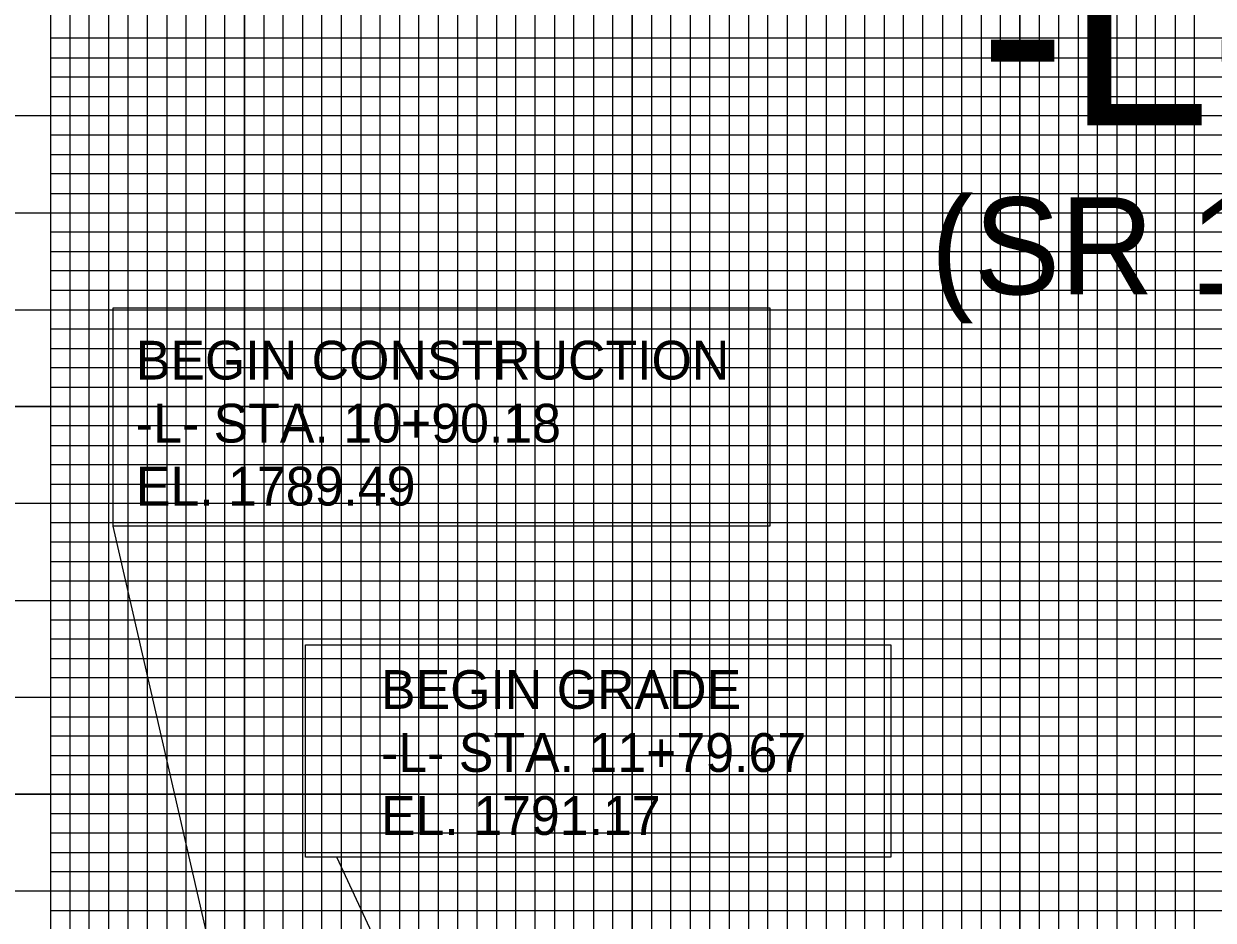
# Model space of a CAD drawing. Extents: x 572269 to 579912, y -56875 to -49627.
# Drawn here: x 573877.8 to 574184.5, y -53080.2 to -52849 of the extents above; entities that cross this region are included whole.
import ezdxf

# ---------------------------------------------------------------- set-up
doc = ezdxf.new("R2010")
doc.units = 0
for name, color, linetype in [('Prop Grid Mask', 7, 'Continuous'), ('Prop PFL Text', 7, 'Continuous'), ('Sheet Cutting Line CELL', 7, 'Continuous'), ('Sheet DOT Grid CELL', 7, 'Continuous'), ('Sheet Layout Profile Border', 7, 'Continuous'), ('Sheet Profile Grid Major CELL', 7, 'Continuous'), ('Sheet Profile Grid Middle CELL', 7, 'Continuous'), ('Sheet Profile Grid Minor CELL', 7, 'Continuous')]:
    doc.layers.add(name, color=color, linetype=linetype)

# ---------------------------------------------------------------- blocks, each defined once
blk = doc.blocks.new('PROFILE SHEET SINGLE')
at = {"layer": 'Sheet DOT Grid CELL'}
for p, q in [((1, 21), (1, 0.5)), ((2, 21), (2, 0.5)), ((3, 21), (3, 0.5)), ((4, 21), (4, 0.5)), ((5, 21), (5, 0.5)), ((6, 21), (6, 0.5)), ((0, 18.5), (25.999, 18.5)), ((0, 17.5), (30, 17.5)), ((0, 16.5), (30, 16.5)), ((0, 15.5), (30, 15.5))]:
    blk.add_line(p, q, dxfattribs=at)
at = {"layer": 'Sheet Profile Grid Major CELL'}
for points in [[(1, 21), (1, 0.5), (2, 0.5), (2, 21)], [(3, 21), (3, 0.5), (4, 0.5), (4, 21)], [(5, 21), (5, 0.5), (6, 0.5), (6, 21)], [(30, 17.5), (0, 17.5), (0, 18.5), (25.999, 18.5)], [(30, 15.5), (0, 15.5), (0, 16.5), (30, 16.5)]]:
    blk.add_lwpolyline(points, dxfattribs=at)
at = {"layer": 'Sheet Profile Grid Middle CELL'}
for points in [[(1.5, 0.5), (1.5, 21)], [(2.5, 21), (2.5, 0.5), (3.5, 0.5), (3.5, 21)], [(4.5, 21), (4.5, 0.5), (5.5, 0.5), (5.5, 21)], [(6.5, 21), (6.5, 0.5), (7.5, 0.5), (7.5, 21)], [(25.999, 19), (0, 19), (0, 17.999), (30, 17.999)], [(30, 17), (0, 17), (0, 16), (30, 16)], [(30, 15), (0, 15), (0, 14), (30, 14)]]:
    blk.add_lwpolyline(points, dxfattribs=at)
at = {"layer": 'Sheet Profile Grid Minor CELL'}
for p, q in [((29, 17.4), (1, 17.4)), ((1, 17.4), (1, 17.3)), ((1, 17.3), (29, 17.3)), ((29, 16.9), (1, 16.9))]:
    blk.add_line(p, q, dxfattribs=at)
for points in [[(1.1, 21), (1.1, 0.5), (1.2, 0.5), (1.2, 21)], [(1.3, 21), (1.3, 0.5), (1.4, 0.5), (1.4, 21)], [(1.6, 21), (1.6, 0.5), (1.7, 0.5), (1.7, 21)], [(1.8, 21), (1.8, 0.5), (1.9, 0.5), (1.9, 21)], [(2.1, 21), (2.1, 0.5), (2.2, 0.5), (2.2, 21)], [(2.3, 21), (2.3, 0.5), (2.4, 0.5), (2.4, 21)], [(2.6, 21), (2.6, 0.5), (2.7, 0.5), (2.7, 21)], [(2.8, 21), (2.8, 0.5), (2.9, 0.5), (2.9, 21)], [(3.1, 21), (3.1, 0.5), (3.2, 0.5), (3.2, 21)], [(3.3, 21), (3.3, 0.5), (3.4, 0.5), (3.4, 21)], [(3.6, 21), (3.6, 0.5), (3.7, 0.5), (3.7, 21)], [(3.8, 21), (3.8, 0.5), (3.9, 0.5), (3.9, 21)], [(4.1, 21), (4.1, 0.5), (4.2, 0.5), (4.2, 21)], [(4.3, 21), (4.3, 0.5)], [(4.3, 0.5), (4.4, 0.5), (4.4, 21)], [(4.6, 21), (4.6, 0.5), (4.7, 0.5), (4.7, 21)], [(4.8, 21), (4.8, 0.5), (4.9, 0.5), (4.9, 21)], [(5.1, 21), (5.1, 0.5), (5.2, 0.5), (5.2, 21)], [(5.3, 21), (5.3, 0.5), (5.4, 0.5), (5.4, 21)], [(5.6, 21), (5.6, 0.5), (5.7, 0.5), (5.7, 21)], [(5.8, 21), (5.8, 0.5), (5.9, 0.5), (5.9, 21)], [(6.1, 21), (6.1, 0.5), (6.2, 0.5), (6.2, 21)], [(6.3, 21), (6.3, 0.5), (6.4, 0.5), (6.4, 21)], [(6.6, 21), (6.6, 0.5), (6.7, 0.5), (6.7, 21)], [(6.8, 21), (6.8, 0.5), (6.9, 0.5), (6.9, 21)], [(25.999, 19.4), (1, 19.4), (1, 19.3), (25.999, 19.3)], [(25.999, 19.2), (1, 19.2), (1, 19.1), (25.999, 19.1)], [(25.999, 18.9), (1, 18.9), (1, 18.8), (25.999, 18.8)], [(25.999, 18.7), (1, 18.7), (1, 18.6), (25.999, 18.6)], [(25.999, 18.4), (1, 18.4), (1, 18.3), (25.999, 18.3)], [(29, 18.2), (1, 18.2), (1, 18.2), (1, 17.8), (29, 17.8)], [(1, 18.1), (29, 18.1)], [(29, 17.9), (1, 17.9)], [(29, 17.7), (1, 17.7), (1, 17.6), (29, 17.6)], [(29, 17.2), (1, 17.2), (1, 17.1), (29, 17.1)], [(29, 16.8), (1, 16.8), (1, 16.7), (29, 16.7)], [(29, 16.6), (1, 16.6)], [(1, 16.4), (29, 16.4)], [(29, 16.3), (1, 16.3), (1, 16.2), (29, 16.2)], [(29, 16.1), (1, 16.1), (1, 15.9), (29, 15.9)], [(29, 15.8), (1, 15.8), (1, 15.7), (29, 15.7)], [(29, 15.6), (1, 15.6), (1, 15.4), (29, 15.4)], [(29, 15.3), (1, 15.3), (1, 15.2), (29, 15.2)], [(29, 15.1), (1, 15.1), (1, 14.9), (29, 14.9)]]:
    blk.add_lwpolyline(points, dxfattribs=at)

msp = doc.modelspace()

# ---------------------------------------------------------------- linework, layer by layer
at = {"layer": 'Prop Grid Mask'}
for points in [[(573900.84, -52922.26), (574070.17, -52922.26), (574070.17, -52978.52), (573900.84, -52978.52)], [(573950.44, -53009.16), (574101.43, -53009.16), (574101.43, -53063.91), (573950.44, -53063.91)]]:
    msp.add_lwpolyline(points, close=True, dxfattribs=at)
at = {"layer": 'Prop PFL Text'}
for p, q in [((573974.87, -53300.26), (573900.84, -52978.52)), ((574064.36, -53291.86), (573958.57, -53063.91))]:
    msp.add_line(p, q, dxfattribs=at)
at = {"layer": 'Sheet Layout Profile Border'}
msp.add_lwpolyline([(573884.69, -52772.71), (573884.69, -53797.71), (575284.69, -53797.71), (575284.69, -52910.26), (575134.64, -52910.26), (575134.64, -52772.71)], close=True, dxfattribs=at)

# ---------------------------------------------------------------- block references
at = {"layer": 'Sheet Cutting Line CELL', "xscale": 50, "yscale": 50}
msp.add_blockref('PROFILE SHEET SINGLE', (573834.69, -53822.71), dxfattribs=at)

# ---------------------------------------------------------------- texts
at = {"layer": 'Prop PFL Text'}
for s, height, p in [('-L-', 50, (574124.3, -52875.2)), ('(SR 1300)', 25, (574111.64, -52918.75)), ('BEGIN CONSTRUCTION', 10, (573906.7, -52940.74)), ('-L- STA. 10+90.18', 10, (573906.7, -52956.99)), ('EL. 1789.49', 10, (573906.7, -52973.24)), ('BEGIN GRADE ', 10, (573969.92, -53025.7)), ('-L- STA. 11+79.67', 10, (573969.92, -53041.95)), ('EL. 1791.17', 10, (573969.92, -53058.2))]:
    msp.add_text(s, height=height, dxfattribs=at).set_placement(p)

doc.saveas('drawing.dxf')
